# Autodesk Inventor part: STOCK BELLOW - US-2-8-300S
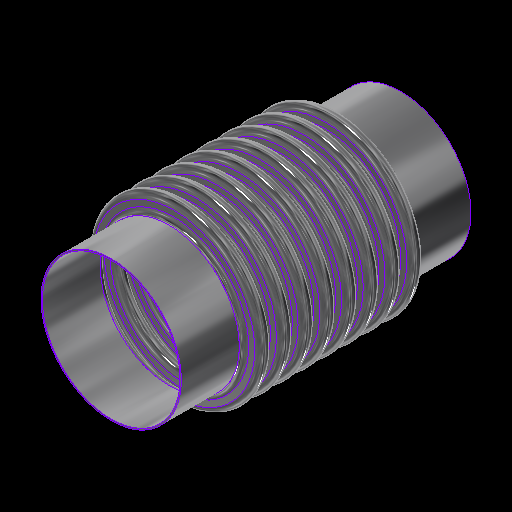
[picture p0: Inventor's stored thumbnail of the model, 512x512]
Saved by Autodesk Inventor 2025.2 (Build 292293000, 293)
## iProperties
Category: 24 GA (0.024 THICK)
RuleStatus: InUse
Created: 2024-01
Part Number: STOCK BELLOW - US-2-8-300S
Project: =STOCK BELLOWS: <Stock Number><SFILL>
Material: ASTM A240-304
Description: =STOCK BELLOWS: <Stock Number>, <SID_> I.D., <SOD_> O.D., <SPLY_> PLY, <Category>, <SNET_CONS> CONS.<PITCH_><STANGENT_> TANGENT<SFILL>
Document SubType Name: Sheet Metal
Designer: GS
Stock Number: U.S-2-8-300S
Surface Area: 890.924 cm^2
Volume: 26.942 cm^3
Sheet Metal Rule: Default
Appearance: STAINLESS STEEL
Mass: 217.079 g
Density: 8.05729 g/cm^3
THK: 0.036
ID: 3.500
OD: 4.250
CONS_: 2
PITCH: 0.500
TANGENT: 0.500
BELLOWS_UPSET: 0.000
d79: 1.000
d82: 1.000
d83: 26.000
d84: 24.000
d174: 8
d214: 8
STHK_: 0.024
SID_: 2.375
SOD_: 3.000
SPITCH_: 0.375
STANGENT__: 1.000
SBELLOWS_UPSET_: 0.000
SDIFF_TAN: 1.000
d252: 2
d275: 2
d287: 0.050
d289: 0.500
d290: 0.000
SOD_NECK: 2 7/16
PLY: 1
PSET: 4.178
PBAR: 1.035
COUNTER: 1.500
NET_TUBE: 3.071
CONS: 2
S_CONS: 0
NET_CONS: 2
ID_M: 88.90 mm
OD_M: 107.95 mm
THK_M: 0.91 mm
ID_U: 3.500 in
OD_U: 4.250 in
THK_U: 0.036 in
TANGENT2: 0.500
TAN_TO_TAN: 1.000 in
d80: 2.571
d81: 10
SID: 2.375
SCONS_: 8
SPITCH: 0.250
STANGENT_: 1.000
SBELLOWS_UPSET: 0.000
SNET_CONS: 8
SS_CONS: 0
SCONS: 8
d190: 8
d191: 1
d192: 1
d193: 8
d194: 0
SIZE: 2.00
PRESSURE: 300
d230: 8
STANGENT: 4.000
SPLY_: 1
d233: 8
d234: 0
d263: 2
d265: 1
d268: 2
d269: 0
d286: 2
d288: 1
d291: 2
d292: 0
SREROLL: 0.750
BLETP: 0.000 ul
PRES_Copy: 85
MATTABLE: 20 GA (0.036 THICK)
PART_NUMBER: U.S-2-8-300S
PITCH_: =, <SPITCH_> PITCH,
CFILL: .
SFILL: .
MESH: ,
COMP: 0.32
EXT: 0.16
LAT: 0.12
ANG: 573
ASR: 2511
LSR: 3022
ANSR: 40
PRES: 300
COMPM: 3.2
EXTM: 1.6
LATM: 1.20
ASRM: 439.751
PRESM: 20.684
LSRM: 529.243
ANSRM: 7.005
TEMPMIN: 20
TEMPMAX: 800
TEMPMINM: -7
TEMPMAXM: 427
WEIGHTM: 0.217
WEIGHT: 0.479
Author: GS
Keywords: 20 GA (0.036 THICK)
Comments: =STOCK BELLOW - <STOCK NUMBER>
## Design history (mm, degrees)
sketch "Sketch2"
  geometry: L1 (0, -177.245)-(0, 562.856) reference; L2 (45.364, 0)-(44.45, 0); L3 (48.082, -2.718)-(50.343, -2.718); L4 (48.082, -3.632)-(50.343, -3.632); L5 (50.343, -9.982)-(48.082, -9.982); L6 (50.343, -9.068)-(48.082, -9.068); L7 (45.364, -12.7)-(44.45, -12.7); L8 (48.082, 0)-(48.082, -12.7); L9 (50.343, -6.35)-(53.975, -6.35); L10 (44.45, 0)-(44.45, -12.7); L11 (20.376, 102.841)-(20.376, 101.926); L12 (58.262, 457.127)-(58.262, 349.177); L13 (58.262, 444.427)-(58.262, 336.477); L14 (93.133, -58.817)-(93.133, -71.517); L15 (118.746, -66.401)-(118.746, -66.401); L16 (50.343, -9.068)-(50.343, -9.982); L17 (48.082, -9.068)-(48.082, -9.982); L18 (48.082, -9.525)-(50.343, -9.525); L19 (53.975, 0)-(53.975, -12.7); L20 (-50.343, -9.068)-(-50.343, -9.982); L21 (-50.343, -2.718)-(-48.082, -2.718); L22 (-50.343, -3.632)-(-48.082, -3.632); L23 (-48.082, -9.068)-(-50.343, -9.068); L24 (-50.343, -9.525)-(-48.082, -9.525); L25 (-48.082, -9.982)-(-50.343, -9.982); L26 (-48.082, -9.068)-(-48.082, -9.982); L27 (-44.45, 0.653)-(-44.45, -12.047); L28 (-48.082, -6.35)-(-44.45, -6.35); L29 (-50.343, 0.653)-(-50.343, -12.7); L30 (-53.061, 0)-(-53.975, 0); L31 (-53.975, 0)-(-53.975, -12.7); L32 (-53.061, -12.7)-(-53.975, -12.7); A1 r 2.718 centre (48.082, 0) between (45.364, 0) and (48.082, -2.718); A2 r 3.632 centre (48.082, 0) between (44.45, 0) and (48.082, -3.632); A3 r 3.632 centre (50.343, -6.35) between (50.343, -9.982) and (50.343, -2.718); A4 r 2.718 centre (50.343, -6.35) between (50.343, -9.068) and (50.343, -3.632); A5 r 2.718 centre (48.082, -12.7) between (48.082, -9.982) and (45.364, -12.7); A6 r 3.632 centre (48.082, -12.7) between (48.082, -9.068) and (44.45, -12.7); A7 r 3.175 centre (50.343, -6.35) between (50.343, -9.525) and (53.518, -6.35); A8 r 3.175 centre (48.082, -12.7) between (48.082, -9.525) and (44.907, -12.7); A9 r 2.718 centre (-50.343, -12.7) between (-50.343, -9.982) and (-53.061, -12.7); A10 r 2.718 centre (-48.082, -6.35) between (-48.082, -9.068) and (-48.082, -3.632); A11 r 3.175 centre (-48.082, -6.35) between (-48.082, -9.525) and (-44.907, -6.35); A12 r 3.632 centre (-48.082, -6.35) between (-48.082, -9.982) and (-48.082, -2.718); A13 r 3.175 centre (-50.343, -12.7) between (-50.343, -9.525) and (-53.518, -12.7); A14 r 3.632 centre (-50.343, -12.7) between (-50.343, -9.068) and (-53.975, -12.7); A15 r 2.718 centre (-50.343, 0) between (-53.061, 0) and (-50.343, -2.718); A16 r 3.632 centre (-50.343, 0) between (-53.975, 0) and (-50.343, -3.632); 10 further points
  constraints: 62 end point, 38 point on circle, 20 tangent, 16 centre point, 12 parallel, 9 midpoint, 7 vertical, 6 coincident, 6 concentric, 6 point on line, 4 equal radius, 4 perpendicular, 3 horizontal, 1 collinear, 1 horizontal alignment, 10 other
  dimensions: "THK" = 0.9144 distance of L11.start L11.end; "ID" = 88.9 distance of L11.end point (20.376, 13.026); "OD" = 107.95 distance of L12.start L12.end; "PITCH" = 12.7 distance of L12.start L13.start; "TANGENT" = 12.7 distance of L14.start L14.end; "BELLOWS_UPSET" = 0 distance of L15.start L15.end; "d43" = 88.9 diameter of L10 L1 (= ID); "d44" = 107.95 diameter of L9.end L1 (= OD); "d45" = 0.9144 distance between parallel lines of L5 L6 (computed from THK, PLY); "d46" = 3.6322 radius of A3 (computed from PITCH, THK, PLY); "UPSET_PITCH" = 12.7 distance of L2.end L7.end (derived); "SIDEWALL_ANGLE" = 360 deg dimension on L3 L9 (derived); "CON_GAP" = 5.4356 distance of point (48.082, -9.068) point (48.082, -3.632) (derived); "TAN1" = 4.98728 dimension on A8 (derived); "TAN2" = 4.98728 dimension on A7 (derived); "LEG1" = 2.2606 distance of L18.start L18.end (derived); "d278" = 0.9144 distance between parallel lines of L25 L23 (derived); "d279" = 3.6322 radius of A12 (derived); "d280" = 12.7 distance of L30.end L31.end (derived); "d281" = 360 deg dimension on L21 L28 (derived); "d282" = 5.4356 distance of point (-50.343, -9.068) point (-50.343, -3.632) (derived); "d283" = 4.98728 dimension on A13 (derived); "d284" = 4.98728 dimension on A11 (derived); "d285" = 2.2606 distance of L24.start L24.end (derived); "d293" = 88.9 diameter of L27 L1 (derived); "d294" = 107.95 diameter of L31 L1 (derived)
  node "Sketch Rectangular Pattern1" dims "d31" = 25.4, "ID" = 88.9
  node "Sketch Rectangular Pattern2" dims "d39" = 25.4, "PITCH" = 12.7
revolve "CONS" stored, may be unused: angle "d48" = 90 deg
node "BELLOW MIDPLANE"
pattern_linear "Rectangular Pattern2" dims "d52" = 12.7 (= UPSET_PITCH)
sketch "Sketch5"
  geometry: C1 r 45.364 at (0, 0) reference; C2 r 44.45 at (0, 0) reference
extrude "TANGENT" new body sketch "Sketch5" distance "d53" = 12.7 (= TANGENT); taper "d54" = 0 deg
revolve "SAMETAN" stored, may be unused: angle "d65" = 90 deg
revolve "DIFFTAN" stored, may be unused: angle "d70" = 90 deg
sketch "Sketch9"
  geometry: L1 (53.319, 0)-(-53.319, 0) reference; L2 (0, -17.78)-(0, 17.78) reference; L3 (38.085, 0)-(-38.085, 0); L4 (38.085, -11.906)-(38.085, 11.906); L5 (25.385, -11.906)-(25.385, 11.906); L6 (13.15, 11.906)-(13.15, -11.906); L7 (-25.385, -11.906)-(-25.385, 11.906); L8 (-38.085, -11.906)-(-38.085, 11.906); L9 (37.291, -11.906)-(37.291, 11.906); L10 (38.085, -11.906)-(37.291, -11.906); L11 (38.085, 11.906)-(37.291, 11.906); L12 (13.546, 11.906)-(12.753, 11.906); L13 (12.753, 11.906)-(12.753, -11.906); L14 (12.753, -11.906)-(13.546, -11.906); L15 (13.546, -11.906)-(13.546, 11.906); L16 (-13.546, 11.906)-(-13.546, -11.906); L17 (-13.15, 11.906)-(-13.15, -11.906); L18 (-13.546, -11.906)-(-12.753, -11.906); L19 (-12.753, -11.906)-(-12.753, 11.906); L20 (-12.753, 11.906)-(-13.546, 11.906); L21 (-38.085, -11.906)-(-37.291, -11.906); L22 (-37.291, -11.906)-(-37.291, 11.906); L23 (-37.291, 11.906)-(-38.085, 11.906); L24 (-38.085, 11.906)-(-38.085, -11.906); L25 (38.085, -0.397)-(-38.085, -0.397); L26 (-38.085, -0.397)-(-38.085, 0.397); L27 (-38.085, 0.397)-(38.085, 0.397); L28 (38.085, 0.397)-(38.085, -0.397); L29 (-38.085, 11.906)-(38.085, 11.906); L30 (38.085, 11.906)-(38.085, 12.7); L31 (38.085, 12.7)-(-38.085, 12.7); L32 (-38.085, 12.7)-(-38.085, 11.906); L33 (38.085, -11.906)-(-38.085, -11.906); L34 (-38.085, -11.906)-(-38.085, -12.7); L35 (-38.085, -12.7)-(38.085, -12.7); L36 (38.085, -12.7)-(38.085, -11.906); 30 further points
  constraints: 68 end point, 13 midpoint, 13 parallel, 8 horizontal, 7 perpendicular, 6 equal length, 3 point on line, 2 vertical, 14 other
  dimensions: "d115" = 23.8125 distance of L4.start L4.end (derived); "d116" = 12.7 distance between parallel lines of L4 L5 (derived); "d117" = 12.23516 distance between parallel lines of L5 L6 (derived); "d125" = 38.53427 distance between parallel lines of L7 L6 (derived); "d127" = 12.7 distance between parallel lines of L8 L7 (derived); "d128" = 24.93516 distance between parallel lines of L6 L4 (derived); "d130" = 76.16943 distance between parallel lines of L8 L4 (derived); "RULER_THK" = 0.79375 distance between parallel lines of L4 L9; "d135" = 0.79375 distance of L13.end L14.end (derived); "d138" = 26.29911 distance of L13.end L16.end (derived); "d143" = 0.79375 distance of L22.end L8.end (derived); "d144" = 0.79375 distance between parallel lines of L27 L25 (derived)
extrude "RULER" join sketch "Sketch9" distance "d149" = 0.79375 (derived); taper "d150" = 0 deg
extrude "BARS" join sketch "Sketch9" distance "d151" = 0.79375 (derived); taper "d152" = 0 deg
pattern_linear "Rectangular Pattern4" dims "d155" = 26.29911 (derived)
sketch "Sketch13"
  geometry: L1 (93.149, -52.467)-(93.149, -77.867); L2 (30.772, 0)-(30.162, 0); L3 (30.772, -9.525)-(30.162, -9.525); L4 (35.414, -7.449)-(32.849, -7.449); L5 (35.414, -6.839)-(32.849, -6.839); L6 (35.414, -4.763)-(38.1, -4.762); L7 (32.849, -2.076)-(35.414, -2.076); L8 (32.849, 0)-(32.849, -9.525); L9 (30.162, 0)-(30.162, -9.525); L10 (58.254, -420.231)-(58.254, -496.431); L11 (58.254, -429.756)-(58.254, -505.956); L12 (58.254, -448.806)-(58.254, -525.006); L13 (58.254, -458.331)-(58.254, -534.531); L14 (58.254, -467.856)-(58.254, -544.056); L15 (58.254, -477.381)-(58.254, -553.581); L16 (58.254, -486.906)-(58.254, -563.106); L17 (58.254, -439.281)-(58.254, -515.481); L18 (20.376, 102.536)-(20.376, 101.926); L19 (32.849, -2.686)-(35.414, -2.686); L20 (0, -696.234)-(0, 235.664) reference; L21 (-23.752, 0)-(142.514, 0) reference; A1 r 2.076 centre (32.849, 0) between (30.772, 0) and (32.849, -2.076); A2 r 2.076 centre (32.849, -9.525) between (32.849, -7.449) and (30.772, -9.525); A3 r 2.686 centre (32.849, -9.525) between (32.849, -6.839) and (30.162, -9.525); A4 r 2.076 centre (35.414, -4.763) between (35.414, -6.839) and (35.414, -2.686); A5 r 2.686 centre (35.414, -4.763) between (35.414, -7.449) and (35.414, -2.076); A6 r 2.686 centre (32.849, 0) between (30.162, 0) and (32.849, -2.686); 6 further points; 1 other entity
  constraints: 38 end point, 15 point on circle, 9 tangent, 6 centre point, 6 parallel, 5 vertical alignment, 4 point on line, 4 vertical, 3 coincident, 3 concentric, 2 collinear, 2 equal radius, 1 horizontal, 1 perpendicular, 23 other
  dimensions: "SBELLOWS_UPSET_" = 0 distance of point (118.762, -66.401) point (118.762, -66.401); "STOTAL_THK_BELLOW__" = 0.6096 distance between parallel lines of L4 L5 (derived); "d224" = 2.68605 radius of A5 (derived); "d225" = 9.525 distance of L2.end L3.end (derived); "SSIDEWALL_ANGLE_" = 0 deg angle of L7 L6 (derived); "SSCON_GAP_" = 4.1529 distance of point (32.849, -6.839) point (32.849, -2.686) (derived); "d235" = 60.325 diameter of L9 L20 (derived); "d236" = 76.2 diameter of L6.end L20 (derived)
  node "Sketch Rectangular Pattern4" dims "d228" = 25.4
  node "Sketch Rectangular Pattern5" dims "d229" = 25.4
revolve "SBELLOW" stored, may be unused: angle "d197" = 90 deg
pattern_linear "Rectangular Pattern5" dims "d204" = 9.525 (derived)
revolve "STANGENT" stored, may be unused: angle "d240" = 90 deg
revolve "SSAMETAN" stored, may be unused: angle "d241" = 90 deg
revolve "SDIFFTAN" stored, may be unused: angle "d246" = 90 deg
revolve "INVCON" stored, may be unused: angle "d295" = 90 deg
pattern_linear "Rectangular Pattern6" dims "d298" = 12.7 (derived)
revolve "INVTANGENT" stored, may be unused: angle "d302" = 90 deg
revolve "INVSAMETAN" stored, may be unused: angle "d307" = 90 deg
revolve "INVDIFFTAN" stored, may be unused: angle "d312" = 90 deg
sketch "ID BELLOW MOUNT CALC"
  geometry: L1 (44.45, 0)-(38.1, 0); L2 (38.1, 0)-(38.1, 12.7); L3 (38.1, 12.7)-(44.45, 12.7); L4 (44.45, 12.7)-(44.45, 0); L5 (36.513, 12.7)-(35.598, 12.7); L6 (35.598, 12.7)-(35.598, 0); L7 (35.598, 0)-(36.513, 0); L8 (36.513, 0)-(36.513, 12.7); L9 (0, -2.54)-(0, 15.24) reference; L10 (-8.89, 0)-(53.34, 0) reference; 1 further point
  constraints: 16 end point, 5 parallel, 2 collinear, 2 horizontal, 2 perpendicular
  dimensions: "d314" = 12.7 distance of L5.end L6.end (derived); "d315" = 0.9144 distance of L5.start L5.end (derived); "IG" = 1.5875 distance between parallel lines of L2 L8; "PIPE_OD" = 88.9 diameter of L4 L9; "PIPE_WALL" = 6.35 distance of L2.end L3.end; "ID_MT_BELLOW" = 71.1962 diameter of L6 L9 (derived)
revolve "CFILL" stored, may be unused: angle "d320" = 90 deg
pattern_linear "Rectangular Pattern7" dims "d323" = 12.7 (derived)
revolve "SFILL" stored, may be unused: angle "d324" = 90 deg
pattern_linear "Rectangular Pattern8" dims "d327" = 9.525 (derived)
node "STOCK BELLOW MIDPLANE"
node "BELLOW"
sketch "Sketch6"
  geometry: L1 (-12.7, 45.364)-(0, 45.364); L2 (0, 45.364)-(0, 44.45); L3 (0, 44.45)-(-12.7, 44.45); L4 (-12.7, 44.45)-(-12.7, 45.364); L5 (10.16, 0)-(-60.96, 0) reference; L6 (-38.1, -89.422)-(-38.1, 153.44) reference; 1 further point
  constraints: 8 end point, 2 parallel, 1 horizontal, 1 perpendicular
  dimensions: "d61" = 12.7 distance of L2.end L3.end (derived); "d62" = 0.9144 distance of L1.end L2.end (derived); "d63" = 88.9 diameter of L3 L5 (derived); "d64" = 25.4 distance between parallel lines of L4 L6 (derived)
sketch "Sketch12"
  geometry: 1 further point
sketch "Sketch14"
  geometry: L1 (-25.4, 30.772)-(0, 30.772); L2 (0, 30.772)-(0, 30.162); L3 (0, 30.162)-(-25.4, 30.162); L4 (-25.4, 30.162)-(-25.4, 30.772); L5 (5.08, 0)-(-30.48, 0) reference; L6 (0, -8.89)-(0, 53.34) reference; 1 further point
  constraints: 8 end point, 2 parallel, 1 collinear, 1 horizontal, 1 perpendicular
  dimensions: "d237" = 0.6096 distance of L3.end L1.start (derived); "d238" = 60.325 diameter of L3 L5 (derived); "d239" = 25.4 distance of L1.start L1.end (derived); "SOD_NECK" = 61.5442 diameter of L1 L5 (derived)
sketch "Sketch15"
  geometry: L1 (-8.89, 0)-(53.34, 0) reference; L2 (30.163, -76.2)-(30.772, -76.2); L3 (30.772, -76.2)-(30.772, -101.6); L4 (30.772, -101.6)-(30.163, -101.6); L5 (30.163, -101.6)-(30.163, -76.2); L6 (0, -124.46)-(0, 35.56) reference; 1 further point
  constraints: 8 end point, 2 parallel, 1 horizontal, 1 perpendicular
  dimensions: "d205" = 25.4 distance of L4.end L2.start (derived); "d206" = 0.6096 distance of L3.end L4.end (derived); "d207" = 60.325 diameter of L5 L6 (derived); "d208" = 76.2 distance between parallel lines of L1 L2 (derived)
node "TANGENT_"
node "SAME_TAN"
sketch "Sketch8"
  geometry: L1 (45.364, -25.4)-(44.45, -25.4); L2 (44.45, -25.4)-(44.45, -38.1); L3 (44.45, -38.1)-(45.364, -38.1); L4 (45.364, -38.1)-(45.364, -25.4); L5 (0, -48.26)-(0, 22.86) reference; L6 (-89.422, 0)-(153.44, 0) reference; 1 further point
  constraints: 8 end point, 2 parallel, 1 horizontal, 1 perpendicular
  dimensions: "d66" = 88.9 diameter of L2 L5 (derived); "TOTAL_THK_BELLOW" = 0.9144 distance of L2.end L3.end (derived); "d68" = 25.4 distance between parallel lines of L1 L6 (derived); "d69" = 12.7 distance of L1.end L2.end (derived)
node "DIFF_TAN"
node "Sketch Rectangular Pattern3" dims "d138" = 26.29911 (derived), "d141" = 25.4
node "SBELLOW_"
node "STANGENT_"
node "SSAME_TAN"
sketch "Sketch16"
  geometry: L1 (30.772, -76.2)-(30.163, -76.2); L2 (30.163, -76.2)-(30.163, -101.6); L3 (30.163, -101.6)-(30.772, -101.6); L4 (30.772, -101.6)-(30.772, -76.2); L5 (0, -124.46)-(0, 35.56) reference; L6 (-8.89, 0)-(53.34, 0) reference; 1 further point
  constraints: 8 end point, 2 parallel, 1 horizontal, 1 perpendicular
  dimensions: "SDIFF_TAN" = 25.4 distance of L3.end L1.start; "d243" = 0.6096 distance of L2.end L3.end (derived); "d244" = 76.2 distance between parallel lines of L1 L6 (derived); "d245" = 60.325 diameter of L2 L5 (derived)
node "SDIFF_TAN"
body "Solid15"
sketch "Sketch17"
  geometry: L1 (53.975, 12.7)-(53.061, 12.7); L2 (53.061, 12.7)-(53.061, 0); L3 (53.061, 0)-(53.975, 0); L4 (53.975, 0)-(53.975, 12.7); L5 (0, -2.54)-(0, 15.24) reference; L6 (-10.795, 0)-(64.77, 0) reference; 2 further points
  constraints: 8 end point, 2 parallel, 1 horizontal, 1 midpoint, 1 perpendicular, 1 point on line
  dimensions: "INVTANGENT" = 12.7 distance of L3.end L1.start (derived); "d300" = 0.9144 distance of L1.start L1.end (derived); "d301" = 107.95 diameter of L4 L5 (derived)
body "Solid16"
sketch "Sketch18"
  geometry: L1 (53.975, -25.4)-(53.061, -25.4); L2 (53.061, -25.4)-(53.061, -38.1); L3 (53.061, -38.1)-(53.975, -38.1); L4 (53.975, -38.1)-(53.975, -25.4); L5 (-10.795, 0)-(64.77, 0) reference; L6 (0, -48.26)-(0, 22.86) reference; 1 further point
  constraints: 8 end point, 2 parallel, 1 horizontal, 1 perpendicular
  dimensions: "d303" = 25.4 distance between parallel lines of L1 L5 (derived); "d304" = 12.7 distance of L3.end L1.start (derived); "d305" = 0.9144 distance of L2.end L3.end (derived); "d306" = 107.95 diameter of L4 L6 (derived)
body "Solid17"
sketch "Sketch19"
  geometry: L1 (53.975, -25.4)-(53.061, -25.4); L2 (53.061, -25.4)-(53.061, -38.1); L3 (53.061, -38.1)-(53.975, -38.1); L4 (53.975, -38.1)-(53.975, -25.4); L5 (0, -48.26)-(0, 22.86) reference; L6 (-10.795, 0)-(64.77, 0) reference; 1 further point
  constraints: 8 end point, 2 parallel, 1 horizontal, 1 perpendicular
  dimensions: "d308" = 12.7 distance of L1.end L2.end (derived); "d309" = 107.95 diameter of L4 L5 (derived); "d310" = 0.9144 distance of L2.end L3.end (derived); "d311" = 25.4 distance between parallel lines of L1 L6 (derived)
body "Solid18"
body "Solid19"
body "Solid20"
other parameters: "BMPL" = -38.1, "PSET" = 106.1212 (computed from OD, THK, PLY) [user parameter], "PBAR" = 26.29911 (= 0.570796 x PITCH + OD - ID) [user parameter; used in 1 equation term], "COUNTER" = 15 [user parameter], "NET_TUBE" = 77.99823 (computed from CONS_, PBAR, TANGENT) [user parameter], "S_CONS" = 0 [user parameter; used in 1 equation term], "ID_M" = 88.9 (= ID) [user parameter], "OD_M" = 107.95 (= OD) [user parameter], "THK_M" = 0.9144 (= THK) [user parameter], "ID_U" = 88.9 (= ID) [user parameter], "OD_U" = 107.95 (= OD) [user parameter], "THK_U" = 0.9144 (= THK) [user parameter], "D_UNITS" = 0 [user parameter], "TANGENT2" = 12.7 [user parameter], "TAN_TO_TAN" = 25.4 [user parameter], "OD_NECK" = 90.7288 [user parameter], "d79" = 25.4, "d80" = 65.29823 [user parameter], "d82" = 25.4, "d83" = 660.4, "d84" = 609.6, "sa_0" = 4, "FRAME_THK" = 0.79375 [user parameter], "CON_FLAT" = 12.23516 [user parameter], "SID" = 60.325 [user parameter], "SPITCH" = 6.35 [user parameter], "STANGENT_" = 25.4 [user parameter], "SBELLOWS_UPSET" = 0 [user parameter], "SS_CONS" = 0 [user parameter], "STAN_TO_TAN_" = 76.2 [user parameter], "d100" = 0.6096 [user parameter], "d191" = 25.4 [user parameter], "d194" = 0 [user parameter], "STANGENT" = 101.6 [user parameter], "d234" = 0 [user parameter], "SUPSET_PITCH_" = 9.525 [user parameter], "d269" = 0 [user parameter], "d287" = 1.27, "d289" = 12.7, "d290" = 0, "d292" = 0 [user parameter], "Thickness" = 3.048 (derived), "KFactor" = 4.4, "BendRadius" = 3.048 (derived), "BendReliefWidth" = 3.048 (derived), "BendReliefDepth" = 1.524 (derived), "CornerReliefSize" = 12.192 (derived), "SeamGap" = 0.00508, "MinimumRemnant" = 6.096 (derived), "TransitionRadius" = 3.048 (derived), "JacobiRadiusSize" = 3.048 (derived), "GapSize" = 3.048 (derived), "SREROLL" = 19.05 [user parameter], "CUR_STK_PITCH" = 9.525 [user parameter], "d328" = -38.1 (derived), "ASR" = 25110 [user parameter], "LSR" = 30220 [user parameter], "BLETP" = 0 [user parameter], "ASRM" = 4397.5143 [user parameter], "PRESM" = 206.83949 [user parameter], "LSRM" = 5292.4286 [user parameter], "ANSRM" = 70.052 [user parameter], "TEMPMIN" = 2664.83333 [user parameter], "TEMPMAX" = 6998.16667 [user parameter], "TEMPMINM" = 2664.83333 [user parameter], "TEMPMAXM" = 6998.16667 [user parameter], "WEIGHT" = 2.17079 [user parameter], "WEIGHTM" = 0.00217 [user parameter]
